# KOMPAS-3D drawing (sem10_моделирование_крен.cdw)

Views: Вид 1
Referenced files in \\XDEV-LAPTOP\Users\xdev\Desktop\baumanka\sem10\Курсач\pics\: all3.png
Referenced files: modelir1.cdw
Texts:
  Автопилот стабилизации угла крена
  Моделирование
  Hornet
  Моделирование системы ЛА - АП крена
  № реж.
  Результаты:
  L , дБ
  Переходные процесы на всех режимах полета
  Структурная схема системы ЛА-АП крена
  Передаточная функция системы
  Графики переходных процессов
  Microsoft Sans Serif
  tрег = (2 . . 5)с
  Условие по заданию:
  Пашинин С.А.
  Окоемов Б.Н.
  Автопилот крена-
  МГТУ им. Н.Э.Баумана
  Кафедра ИУ2
  Группа ИУ2-102
Dimensions and other numbers on the sheet: 1; 2; 3; 4; 5; 6; 7; 8; 9; 10; 11; 12; 3,2; 3,3; 3,1; 4,2; 0; 4,9; 0,8; 0,2; 0,7; 0,3; 0,488; 0,486; 1:1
